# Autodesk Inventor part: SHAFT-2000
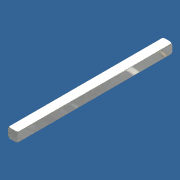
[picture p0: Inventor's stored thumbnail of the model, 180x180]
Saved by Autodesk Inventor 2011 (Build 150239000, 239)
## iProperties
Created: 2007-08
Part Number: SHAFT-2000
Material: Stainless Steel
Document SubType Name: Modeling
Density: 8.08 g/cm^3
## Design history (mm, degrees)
feature "Base1"
workaxis "Work Axis1"
  workplane "Work Plane1"
  workplane "Work Plane2"
body "Solid1"
